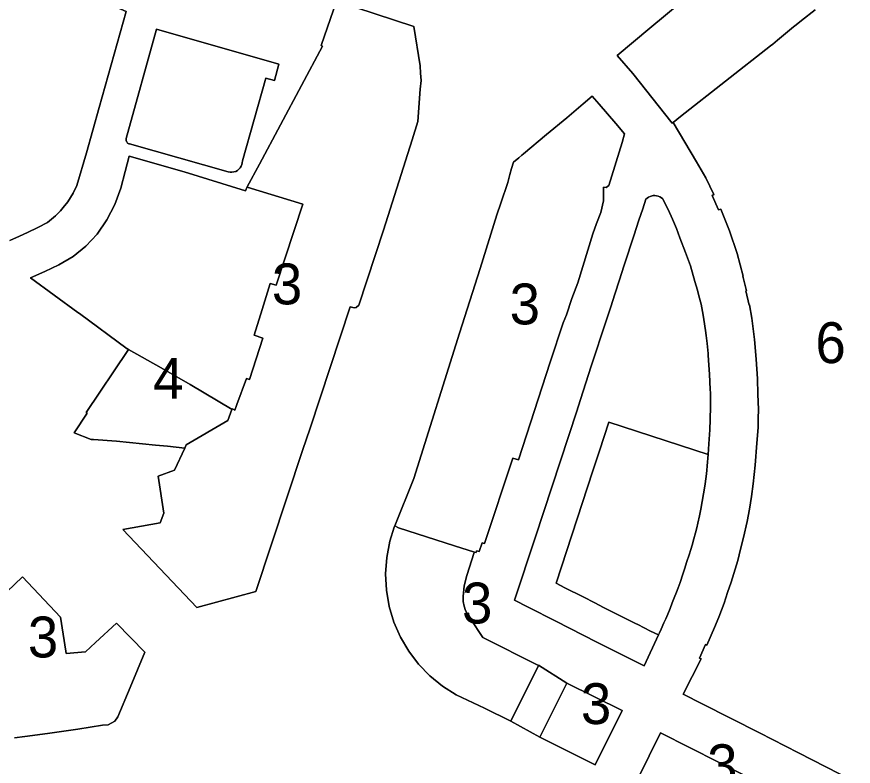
# Model space of a CAD drawing. Extents: x 598968 to 613553, y 4409678 to 4430833.
# Drawn here: x 608676.3 to 608922.1, y 4415660.4 to 4415880.5 of the extents above; entities that cross this region are included whole.
import ezdxf

# ---------------------------------------------------------------- set-up
doc = ezdxf.new("R2010")
doc.units = 0
for name, color, linetype in [('1', 7, 'Continuous'), ("ZONA 3. ILLES  D'EDIFICIS ENTRE MITGERES. EIXAMPLE.", 7, 'Continuous'), ('ZONA 4. CASES UNIFAMILIRAS AÏLLADES EN PARCEL.LES', 7, 'Continuous'), ('ZONA 6. EDIFICIS DE PISOS_ AÏLLATS I EN PARCEL.LES', 7, 'Continuous')]:
    doc.layers.add(name, color=color, linetype=linetype)

msp = doc.modelspace()

# ---------------------------------------------------------------- linework, layer by layer
at = {"layer": '1'}
for points in [[(608665.6671, 4415901.5846), (608685.7511, 4415892.1019), (608687.5781, 4415891.2393), (608708.4875, 4415882.0646), (608700.4769, 4415853.8357), (608696.8316, 4415840.5531), (608693.967, 4415830.9559), (608692.8471, 4415828.6759), (608691.2766, 4415826.1275), (608689.9771, 4415824.4759), (608689.1371, 4415823.5159), (608687.6621, 4415822.0085), (608685.3272, 4415820.1358), (608682.4791, 4415818.601), (608679.4873, 4415817.1158), (608677.0973, 4415816.0357), (608674.2812, 4415814.8108)], [(608674.2812, 4415814.8108), (608677.0973, 4415816.0357), (608679.4873, 4415817.1158), (608682.4791, 4415818.601), (608685.3272, 4415820.1358), (608687.6621, 4415822.0085), (608689.1371, 4415823.5159), (608689.9771, 4415824.4759), (608691.2766, 4415826.1275), (608692.8471, 4415828.6759), (608693.967, 4415830.9559), (608696.8316, 4415840.5531), (608700.4769, 4415853.8357), (608708.4875, 4415882.0646), (608687.5781, 4415891.2393), (608685.7511, 4415892.1019), (608665.6671, 4415901.5846)], [(608922.0848, 4415656.0922), (608905.99, 4415664.3368), (608894.5151, 4415670.2115), (608877.7153, 4415678.7311), (608872.1353, 4415681.591), (608877.3753, 4415691.9507), (608876.9253, 4415692.1009), (608878.7052, 4415696.1109), (608879.1052, 4415695.9309), (608881.2852, 4415701.1359), (608882.5452, 4415704.1709), (608884.1051, 4415708.2709), (608885.1701, 4415711.3809), (608886.2351, 4415714.4908), (608886.9751, 4415716.9608), (608888.125, 4415720.7908), (608888.975, 4415724.1608), (608889.825, 4415727.5307), (608890.885, 4415732.2807), (608891.575, 4415735.9307), (608892.1749, 4415739.6106), (608892.6949, 4415743.3005), (608893.3099, 4415748.8505), (608893.7999, 4415755.2954), (608894.1149, 4415759.8903), (608894.1798, 4415762.5103), (608894.2448, 4415765.1303), (608894.0898, 4415769.6302), (608893.9348, 4415774.1302), (608893.5148, 4415779.9251), (608893.0948, 4415785.72), (608892.2748, 4415791.9799), (608891.6248, 4415795.8898), (608891.4851, 4415795.8585), (608890.5548, 4415800.0098), (608890.7512, 4415800.0631), (608889.6329, 4415804.3124), (608889.7748, 4415804.3497), (608887.9355, 4415811.0367), (608885.7333, 4415817.6132), (608883.1748, 4415824.0593), (608882.5148, 4415823.7693), (608880.6374, 4415828.0603), (608881.1074, 4415828.2848), (608878.7649, 4415833.1899), (608876.0498, 4415837.899), (608869.1849, 4415849.4888), (608869.1711, 4415849.5075), (608868.9091, 4415849.305), (608857.3172, 4415863.8302), (608852.705, 4415869.1482), (608862.2966, 4415877.1663), (608880.7115, 4415892.5602)], [(608880.7115, 4415892.5602), (608862.2966, 4415877.1663), (608852.705, 4415869.1482), (608857.3172, 4415863.8302), (608868.9091, 4415849.305), (608869.1711, 4415849.5075), (608871.3507, 4415851.1924), (608897.7532, 4415871.9606), (608898.4164, 4415872.5136), (608899.7827, 4415873.6528), (608902.7647, 4415876.1135), (608904.5467, 4415877.5412), (608905.354, 4415878.1767), (608906.9198, 4415879.4233), (608910.9111, 4415882.606)], [(608668.766, 4415707.2863), (608677.9789, 4415716.0018), (608689.1975, 4415704.1274), (608690.7464, 4415694.2089), (608690.8575, 4415693.4976), (608696.4874, 4415693.9877), (608699.4574, 4415696.7377), (608705.6247, 4415702.4199), (608713.9672, 4415693.928), (608709.6773, 4415683.528), (608705.9674, 4415674.9031), (608705.1571, 4415673.6697), (608703.1374, 4415672.5681), (608701.5468, 4415672.4145), (608694.2775, 4415671.2879), (608685.3576, 4415669.9578), (608678.6577, 4415669.1077), (608675.6878, 4415668.7176)]]:
    msp.add_lwpolyline(points, dxfattribs=at)
for points in [[(608792.9757, 4415877.627), (608794.8358, 4415866.0772), (608794.9658, 4415863.9272), (608795.0958, 4415861.7773), (608794.8758, 4415859.2273), (608794.1058, 4415849.7874), (608792.4708, 4415844.3325), (608784.0394, 4415817.8481), (608776.7962, 4415795.7978), (608776.0162, 4415795.1628), (608775.4562, 4415795.0278), (608774.2862, 4415795.3177), (608762.4865, 4415759.728), (608760.2965, 4415753.118), (608746.5568, 4415711.7083), (608729.1804, 4415706.969), (608707.4372, 4415729.8974), (608718.4171, 4415731.8376), (608719.477, 4415734.6976), (608717.857, 4415745.5974), (608722.637, 4415747.3874), (608725.6469, 4415753.8374), (608720.607, 4415754.3773), (608717.03, 4415754.7409), (608705.6571, 4415755.897), (608698.8289, 4415756.3612), (608698.1572, 4415756.4069), (608693.206, 4415758.2991), (608697.0451, 4415764.139), (608696.6672, 4415764.3167), (608708.987, 4415782.4767), (608709.1674, 4415782.795), (608708.801, 4415783.0027), (608708.7968, 4415783.0051), (608694.7068, 4415793.3312), (608694.2728, 4415793.6492), (608680.3973, 4415803.8809), (608684.6014, 4415805.6813), (608688.7072, 4415807.696), (608692.8761, 4415810.1175), (608696.645, 4415813.1242), (608699.932, 4415816.6511), (608702.7673, 4415820.8825), (608705.1066, 4415825.407), (608706.9201, 4415830.1667), (608708.1845, 4415835.1008), (608709.303, 4415839.6027), (608725.5287, 4415834.9352), (608743.4712, 4415829.4286), (608743.9875, 4415830.5593), (608744.0068, 4415830.5533), (608747.6016, 4415837.2559), (608766.1502, 4415871.9266), (608765.7528, 4415872.0705), (608770.206, 4415885.1265)], [(608709.4768, 4415843.176), (608709.2696, 4415843.2285), (608709.0741, 4415843.3149), (608708.8958, 4415843.4327), (608708.7396, 4415843.5786), (608708.61, 4415843.7486), (608708.5106, 4415843.9377), (608708.4443, 4415844.1408), (608708.4127, 4415844.3522), (608708.417, 4415844.5659), (608708.4568, 4415844.7759), (608717.3892, 4415876.872), (608753.3367, 4415866.6065), (608752.0263, 4415861.8065), (608749.5363, 4415862.4965), (608742.6165, 4415838.2266), (608742.5856, 4415837.6675), (608742.4603, 4415837.1217), (608742.244, 4415836.6051), (608741.9432, 4415836.1328), (608741.5665, 4415835.7184), (608741.1249, 4415835.374), (608740.6313, 4415835.1096), (608740.0999, 4415834.9329), (608739.5462, 4415834.849), (608738.9863, 4415834.8603), (608738.4365, 4415834.9666)], [(608753.3367, 4415866.6065), (608717.3892, 4415876.872), (608708.4568, 4415844.7759), (608708.417, 4415844.5659), (608708.4127, 4415844.3522), (608708.4443, 4415844.1408), (608708.5106, 4415843.9377), (608708.61, 4415843.7486), (608708.7396, 4415843.5786), (608708.8958, 4415843.4327), (608709.0741, 4415843.3149), (608709.2696, 4415843.2285), (608709.4768, 4415843.176), (608738.4365, 4415834.9666), (608738.9863, 4415834.8603), (608739.5462, 4415834.849), (608740.0999, 4415834.9329), (608740.6313, 4415835.1096), (608741.1249, 4415835.374), (608741.5665, 4415835.7184), (608741.9432, 4415836.1328), (608742.244, 4415836.6051), (608742.4603, 4415837.1217), (608742.5856, 4415837.6675), (608742.6165, 4415838.2266), (608749.5363, 4415862.4965), (608752.0263, 4415861.8065)], [(608812.4654, 4415806.5784), (608817.3756, 4415822.3482), (608818.5327, 4415825.7991), (608820.5456, 4415831.7981), (608821.1547, 4415834.1919), (608821.7102, 4415835.9529), (608822.2955, 4415837.8081), (608823.8361, 4415839.1014), (608824.7465, 4415839.8656), (608825.2123, 4415840.2567), (608831.953, 4415845.9157), (608837.9052, 4415850.8382), (608842.7752, 4415854.9682), (608845.3801, 4415857.1987), (608847.4307, 4415854.8189), (608852.3263, 4415849.1431), (608854.893, 4415846.1663), (608854.1451, 4415843.6186), (608850.2392, 4415830.9477), (608849.4641, 4415830.3639), (608848.7011, 4415830.5188), (608848.7039, 4415826.4498), (608847.8891, 4415822.9861), (608846.6809, 4415819.804), (608845.6053, 4415816.8088), (608841.1754, 4415802.3989), (608839.3754, 4415797.8089), (608837.8504, 4415793.0189), (608836.8854, 4415790.6189), (608833.0655, 4415779.119), (608823.7367, 4415750.4019), (608822.0858, 4415750.9192), (608813.766, 4415725.7994), (608813.3288, 4415725.9349), (608813.056, 4415726.0291), (608812.216, 4415723.4394), (608811.3936, 4415723.6594), (608811.266, 4415723.1394), (608810.7948, 4415723.2858), (608810.7444, 4415723.1336), (608808.556, 4415716.4594), (608807.7803, 4415713.3736), (608807.4461, 4415710.2095), (608807.4963, 4415708.8058), (608807.7432, 4415707.4231), (608808.1819, 4415706.0887), (608808.8036, 4415704.8293), (608809.5961, 4415703.6696), (608813.296, 4415698.1897), (608829.5558, 4415690.0201), (608829.588, 4415690.0856), (608837.9157, 4415684.7703), (608854.162, 4415676.7139), (608846.2557, 4415660.7708), (608829.9683, 4415668.9556), (608821.4948, 4415673.6487), (608821.466, 4415673.5902), (608813.7061, 4415677.47), (608805.3962, 4415681.3198), (608801.3679, 4415683.9017), (608797.6709, 4415686.9391), (608794.3563, 4415690.3898), (608791.4701, 4415694.206), (608789.0523, 4415698.3349), (608787.1363, 4415702.7192), (608785.7608, 4415707.3407), (608784.9421, 4415712.0925), (608784.6918, 4415716.9079), (608785.0134, 4415721.719), (608785.9024, 4415726.4582), (608787.2064, 4415730.6129), (608787.2779, 4415730.8406), (608787.3463, 4415731.0588), (608787.363, 4415731.049), (608793.0161, 4415744.8987), (608806.4059, 4415787.5784)], [(608744.0068, 4415830.5533), (608743.9875, 4415830.5593), (608743.4712, 4415829.4286), (608725.5287, 4415834.9352), (608709.303, 4415839.6027), (608708.1845, 4415835.1008), (608706.9201, 4415830.1667), (608705.1066, 4415825.407), (608702.7673, 4415820.8825), (608699.932, 4415816.6511), (608696.645, 4415813.1242), (608692.8761, 4415810.1175), (608688.7072, 4415807.696), (608684.6014, 4415805.6813), (608680.3973, 4415803.8809), (608694.2728, 4415793.6492), (608694.7068, 4415793.3312), (608708.7968, 4415783.0051), (608708.801, 4415783.0027), (608709.1674, 4415782.795), (608709.1742, 4415782.807), (608718.7341, 4415777.3734), (608718.752, 4415777.3632), (608727.2113, 4415772.5395), (608739.5525, 4415765.1829), (608739.5352, 4415765.1375), (608739.7349, 4415765.3464), (608740.3581, 4415764.9873), (608740.8993, 4415766.3654), (608741.0167, 4415766.6875), (608743.7766, 4415774.2575), (608744.6966, 4415773.9575), (608748.6465, 4415786.1674), (608746.0866, 4415786.9873), (608748.4215, 4415794.5773), (608750.7565, 4415802.1672), (608752.5664, 4415801.6473), (608760.3767, 4415825.4483), (608743.9765, 4415830.4968)], [(608840.8271, 4415764.7093), (608841.2426, 4415765.9879), (608842.7283, 4415770.5526), (608845.1213, 4415777.9042), (608846.6397, 4415782.5694), (608847.9253, 4415786.5192), (608849.6878, 4415791.8175), (608850.8653, 4415795.3573), (608852.0446, 4415799.0167), (608853.406, 4415803.2726), (608854.7061, 4415807.2897), (608855.855, 4415810.8024), (608856.6472, 4415813.2251), (608857.6205, 4415816.2008), (608859.1048, 4415820.7458), (608860.2137, 4415824.1501), (608861.135, 4415826.9789), (608861.915, 4415827.5689), (608862.365, 4415827.7789), (608863.315, 4415828.0089), (608863.56, 4415828.0139), (608863.805, 4415828.0189), (608864.775, 4415827.849), (608865.235, 4415827.669), (608866.055, 4415827.129), (608867.715, 4415823.9191), (608868.955, 4415821.1041), (608870.195, 4415818.2892), (608871.1736, 4415815.6391), (608872.7812, 4415811.2861), (608874.2349, 4415807.3494), (608875.5749, 4415802.8095), (608876.3049, 4415800.1995), (608876.7349, 4415798.5295), (608877.3797, 4415796.0976), (608877.9527, 4415792.916), (608878.1669, 4415791.5695), (608878.6417, 4415788.3662), (608878.865, 4415786.8597), (608879.1115, 4415784.5844), (608879.4291, 4415781.6538), (608879.475, 4415781.2298), (608879.5846, 4415779.5971), (608879.855, 4415775.5699), (608880.0783, 4415771.0537), (608880.125, 4415770.11), (608880.1435, 4415768.7625), (608880.1604, 4415767.5331), (608880.1675, 4415766.0152), (608880.0885, 4415762.2281), (608879.955, 4415759.1901), (608879.6507, 4415755.0622), (608879.4304, 4415751.9321), (608879.1951, 4415748.5902), (608879.042, 4415747.2914), (608878.8312, 4415745.5025), (608878.4951, 4415742.6503), (608877.3151, 4415735.8604), (608876.8846, 4415733.9723), (608876.3842, 4415731.7776), (608876.0763, 4415730.4266), (608875.6908, 4415728.96), (608875.2102, 4415727.1555), (608874.7158, 4415725.2991), (608874.3752, 4415724.0205), (608873.8655, 4415722.4677), (608873.2232, 4415720.5112), (608872.4867, 4415718.2675), (608872.0073, 4415716.8071), (608871.2069, 4415714.3687), (608870.6219, 4415712.8204), (608870.134, 4415711.5564), (608869.4782, 4415709.8572), (608868.9153, 4415708.4006), (608868.2754, 4415706.741), (608867.6153, 4415705.0306), (608867.0013, 4415703.6924), (608866.4526, 4415702.4962), (608865.6141, 4415700.6685), (608865.1133, 4415699.5771), (608864.828, 4415698.9553), (608860.6555, 4415689.8607), (608846.7356, 4415696.8503), (608834.6657, 4415702.985), (608826.6074, 4415707.0808), (608822.5959, 4415709.1198), (608828.6357, 4415727.5096), (608836.0406, 4415750.1094)], [(608879.4304, 4415751.9321), (608879.6507, 4415755.0622), (608879.955, 4415759.1901), (608880.0885, 4415762.2281), (608880.1675, 4415766.0152), (608880.1604, 4415767.5331), (608880.1435, 4415768.7625), (608880.125, 4415770.11), (608880.0783, 4415771.0537), (608879.855, 4415775.5699), (608879.5846, 4415779.5971), (608879.475, 4415781.2298), (608879.4291, 4415781.6538), (608879.1115, 4415784.5844), (608878.865, 4415786.8597), (608878.6417, 4415788.3662), (608878.1669, 4415791.5695), (608877.9527, 4415792.916), (608877.3797, 4415796.0976), (608876.7349, 4415798.5295), (608876.3049, 4415800.1995), (608875.5749, 4415802.8095), (608874.2349, 4415807.3494), (608872.7812, 4415811.2861), (608871.1736, 4415815.6391), (608870.195, 4415818.2892), (608868.955, 4415821.1041), (608867.715, 4415823.9191), (608866.055, 4415827.129), (608865.235, 4415827.669), (608864.775, 4415827.849), (608863.805, 4415828.0189), (608863.56, 4415828.0139), (608863.315, 4415828.0089), (608862.365, 4415827.7789), (608861.915, 4415827.5689), (608861.135, 4415826.9789), (608860.2137, 4415824.1501), (608859.1048, 4415820.7458), (608857.6205, 4415816.2008), (608856.6472, 4415813.2251), (608855.855, 4415810.8024), (608854.7061, 4415807.2897), (608853.406, 4415803.2726), (608852.0446, 4415799.0167), (608850.8653, 4415795.3573), (608849.6878, 4415791.8175), (608847.9253, 4415786.5192), (608846.6397, 4415782.5694), (608845.1213, 4415777.9042), (608842.7283, 4415770.5526), (608841.2426, 4415765.9879), (608840.8271, 4415764.7093), (608836.0406, 4415750.1094), (608828.6357, 4415727.5096), (608822.5959, 4415709.1198), (608826.6074, 4415707.0808), (608834.6657, 4415702.985), (608846.7356, 4415696.8503), (608860.6555, 4415689.8607), (608864.828, 4415698.9553), (608862.5328, 4415700.1079), (608858.7675, 4415701.9985), (608858.0659, 4415702.3509), (608851.2813, 4415705.7629), (608851.2671, 4415705.77), (608848.7204, 4415707.059), (608846.1367, 4415708.3723), (608842.7097, 4415710.114), (608837.3604, 4415712.8329), (608834.7727, 4415714.1481), (608845.6051, 4415747.1867), (608847.5223, 4415753.035), (608850.2681, 4415761.4102)], [(608879.4304, 4415751.9321), (608850.2681, 4415761.4102), (608847.5223, 4415753.035), (608845.6051, 4415747.1867), (608834.7727, 4415714.1481), (608837.3604, 4415712.8329), (608842.7097, 4415710.114), (608846.1367, 4415708.3723), (608848.7204, 4415707.059), (608851.2671, 4415705.77), (608851.2813, 4415705.7629), (608858.0659, 4415702.3509), (608858.7675, 4415701.9985), (608862.5328, 4415700.1079), (608864.828, 4415698.9553), (608865.1133, 4415699.5771), (608865.6141, 4415700.6685), (608866.4526, 4415702.4962), (608867.0013, 4415703.6924), (608867.6153, 4415705.0306), (608868.2754, 4415706.741), (608868.9153, 4415708.4006), (608869.4782, 4415709.8572), (608870.134, 4415711.5564), (608870.6219, 4415712.8204), (608871.2069, 4415714.3687), (608872.0073, 4415716.8071), (608872.4867, 4415718.2675), (608873.2232, 4415720.5112), (608873.8655, 4415722.4677), (608874.3752, 4415724.0205), (608874.7158, 4415725.2991), (608875.2102, 4415727.1555), (608875.6908, 4415728.96), (608876.0763, 4415730.4266), (608876.3842, 4415731.7776), (608876.8846, 4415733.9723), (608877.3151, 4415735.8604), (608878.4951, 4415742.6503), (608878.8312, 4415745.5025), (608879.042, 4415747.2914), (608879.1951, 4415748.5902)], [(608837.9157, 4415684.7703), (608829.588, 4415690.0856), (608829.5558, 4415690.0201), (608821.4948, 4415673.6487), (608829.9683, 4415668.9556)], [(608865.4655, 4415670.151), (608899.5386, 4415652.9888), (608892.7452, 4415639.5019), (608858.7456, 4415656.6811)]]:
    msp.add_lwpolyline(points, close=True, dxfattribs=at)
at = {"layer": "ZONA 3. ILLES  D'EDIFICIS ENTRE MITGERES. EIXAMPLE."}
for points in [[(608725.6469, 4415753.8374), (608722.637, 4415747.3874), (608717.857, 4415745.5974), (608719.477, 4415734.6976), (608718.4171, 4415731.8376), (608707.4372, 4415729.8974), (608729.1804, 4415706.969), (608746.5568, 4415711.7083), (608760.2965, 4415753.118), (608762.4865, 4415759.728), (608774.2862, 4415795.3177), (608775.4562, 4415795.0278), (608776.0162, 4415795.1628), (608776.7962, 4415795.7978), (608784.0394, 4415817.8481), (608792.4708, 4415844.3325), (608794.1058, 4415849.7874), (608794.8758, 4415859.2273), (608795.0958, 4415861.7773), (608794.9658, 4415863.9272), (608794.8358, 4415866.0772), (608792.9757, 4415877.627), (608770.206, 4415885.1265), (608765.7528, 4415872.0705), (608766.1502, 4415871.9266), (608747.6016, 4415837.2559), (608744.0068, 4415830.5533), (608743.9765, 4415830.4968), (608760.3767, 4415825.4483), (608752.5664, 4415801.6473), (608750.7565, 4415802.1672), (608748.4215, 4415794.5773), (608746.0866, 4415786.9873), (608748.6465, 4415786.1674), (608744.6966, 4415773.9575), (608743.7766, 4415774.2575), (608741.0167, 4415766.6875), (608740.8993, 4415766.3654), (608740.3581, 4415764.9873), (608739.7349, 4415765.3464), (608739.5352, 4415765.1375), (608738.3367, 4415761.9875), (608726.1269, 4415754.7774)], [(608810.7948, 4415723.2858), (608811.266, 4415723.1394), (608811.3936, 4415723.6594), (608812.216, 4415723.4394), (608813.056, 4415726.0291), (608813.3288, 4415725.9349), (608813.766, 4415725.7994), (608822.0858, 4415750.9192), (608823.7367, 4415750.4019), (608833.0655, 4415779.119), (608836.8854, 4415790.6189), (608837.8504, 4415793.0189), (608839.3754, 4415797.8089), (608841.1754, 4415802.3989), (608845.6053, 4415816.8088), (608846.6809, 4415819.804), (608847.8891, 4415822.9861), (608848.7039, 4415826.4498), (608848.7011, 4415830.5188), (608849.4641, 4415830.3639), (608850.2392, 4415830.9477), (608854.1451, 4415843.6186), (608854.893, 4415846.1663), (608852.3263, 4415849.1431), (608847.4307, 4415854.8189), (608845.3801, 4415857.1987), (608842.7752, 4415854.9682), (608837.9052, 4415850.8382), (608831.953, 4415845.9157), (608825.2123, 4415840.2567), (608824.7465, 4415839.8656), (608823.8361, 4415839.1014), (608822.2955, 4415837.8081), (608821.7102, 4415835.9529), (608821.1547, 4415834.1919), (608820.5456, 4415831.7981), (608818.5327, 4415825.7991), (608817.3756, 4415822.3482), (608812.4654, 4415806.5784), (608806.4059, 4415787.5784), (608793.0161, 4415744.8987), (608787.363, 4415731.049), (608788.4562, 4415730.4089), (608804.9461, 4415725.1092), (608810.796, 4415723.2894)], [(608787.363, 4415731.049), (608787.3463, 4415731.0588), (608787.2779, 4415730.8406), (608787.2064, 4415730.6129), (608785.9024, 4415726.4582), (608785.0134, 4415721.719), (608784.6918, 4415716.9079), (608784.9421, 4415712.0925), (608785.7608, 4415707.3407), (608787.1363, 4415702.7192), (608789.0523, 4415698.3349), (608791.4701, 4415694.206), (608794.3563, 4415690.3898), (608797.6709, 4415686.9391), (608801.3679, 4415683.9017), (608805.3962, 4415681.3198), (608813.7061, 4415677.47), (608821.466, 4415673.5902), (608821.4948, 4415673.6487), (608829.5558, 4415690.0201), (608813.296, 4415698.1897), (608809.5961, 4415703.6696), (608808.8036, 4415704.8293), (608808.1819, 4415706.0887), (608807.7432, 4415707.4231), (608807.4963, 4415708.8058), (608807.4461, 4415710.2095), (608807.7803, 4415713.3736), (608808.556, 4415716.4594), (608810.7444, 4415723.1336), (608810.7948, 4415723.2858), (608810.796, 4415723.2894), (608804.9461, 4415725.1092), (608788.4562, 4415730.4089)], [(608829.9683, 4415668.9556), (608846.2557, 4415660.7708), (608854.162, 4415676.7139), (608837.9157, 4415684.7703)], [(608899.5386, 4415652.9888), (608865.4655, 4415670.151), (608858.7456, 4415656.6811), (608892.7452, 4415639.5019)]]:
    msp.add_lwpolyline(points, close=True, dxfattribs=at)
msp.add_lwpolyline([(608675.6878, 4415668.7176), (608678.6577, 4415669.1077), (608685.3576, 4415669.9578), (608694.2775, 4415671.2879), (608701.5468, 4415672.4145), (608703.1374, 4415672.5681), (608705.1571, 4415673.6697), (608705.9674, 4415674.9031), (608709.6773, 4415683.528), (608713.9672, 4415693.928), (608705.6247, 4415702.4199), (608699.4574, 4415696.7377), (608696.4874, 4415693.9877), (608690.8575, 4415693.4976), (608690.7464, 4415694.2089), (608689.1975, 4415704.1274), (608677.9789, 4415716.0018), (608668.766, 4415707.2863)], dxfattribs=at)
at = {"layer": 'ZONA 4. CASES UNIFAMILIRAS AÏLLADES EN PARCEL.LES'}
msp.add_lwpolyline([(608739.5352, 4415765.1375), (608739.5525, 4415765.1829), (608727.2113, 4415772.5395), (608718.752, 4415777.3632), (608718.7341, 4415777.3734), (608709.1742, 4415782.807), (608709.1674, 4415782.795), (608708.987, 4415782.4767), (608696.6672, 4415764.3167), (608697.0451, 4415764.139), (608693.206, 4415758.2991), (608698.1572, 4415756.4069), (608698.8289, 4415756.3612), (608705.6571, 4415755.897), (608717.03, 4415754.7409), (608720.607, 4415754.3773), (608725.6469, 4415753.8374), (608726.1269, 4415754.7774), (608738.3367, 4415761.9875)], close=True, dxfattribs=at)
at = {"layer": 'ZONA 6. EDIFICIS DE PISOS_ AÏLLATS I EN PARCEL.LES'}
msp.add_lwpolyline([(608910.9111, 4415882.606), (608906.9198, 4415879.4233), (608905.354, 4415878.1767), (608904.5467, 4415877.5412), (608902.7647, 4415876.1135), (608899.7827, 4415873.6528), (608898.4164, 4415872.5136), (608897.7532, 4415871.9606), (608871.3507, 4415851.1924), (608869.1711, 4415849.5075), (608869.1849, 4415849.4888), (608876.0498, 4415837.899), (608878.7649, 4415833.1899), (608881.1074, 4415828.2848), (608880.6374, 4415828.0603), (608882.5148, 4415823.7693), (608883.1748, 4415824.0593), (608885.7333, 4415817.6132), (608887.9355, 4415811.0367), (608889.7748, 4415804.3497), (608889.6329, 4415804.3124), (608890.7512, 4415800.0631), (608890.5548, 4415800.0098), (608891.4851, 4415795.8585), (608891.6248, 4415795.8898), (608892.2748, 4415791.9799), (608893.0948, 4415785.72), (608893.5148, 4415779.9251), (608893.9348, 4415774.1302), (608894.0898, 4415769.6302), (608894.2448, 4415765.1303), (608894.1798, 4415762.5103), (608894.1149, 4415759.8903), (608893.7999, 4415755.2954), (608893.3099, 4415748.8505), (608892.6949, 4415743.3005), (608892.1749, 4415739.6106), (608891.575, 4415735.9307), (608890.885, 4415732.2807), (608889.825, 4415727.5307), (608888.975, 4415724.1608), (608888.125, 4415720.7908), (608886.9751, 4415716.9608), (608886.2351, 4415714.4908), (608885.1701, 4415711.3809), (608884.1051, 4415708.2709), (608882.5452, 4415704.1709), (608881.2852, 4415701.1359), (608879.1052, 4415695.9309), (608878.7052, 4415696.1109), (608876.9253, 4415692.1009), (608877.3753, 4415691.9507), (608872.1353, 4415681.591), (608877.7153, 4415678.7311), (608894.5151, 4415670.2115), (608905.99, 4415664.3368), (608922.0848, 4415656.0922)], dxfattribs=at)

# ---------------------------------------------------------------- texts
at = {"layer": "ZONA 3. ILLES  D'EDIFICIS ENTRE MITGERES. EIXAMPLE."}
for p in [(608751.2665, 4415796.0477), (608821.128, 4415790.169), (608807.1238, 4415702.3245), (608679.5697, 4415692.3492), (608842.0651, 4415672.7706), (608879.1421, 4415654.8265)]:
    msp.add_text('3', height=12, dxfattribs=at).set_placement(p)
at = {"layer": 'ZONA 4. CASES UNIFAMILIRAS AÏLLADES EN PARCEL.LES'}
msp.add_text('4', height=12, dxfattribs=at).set_placement((608716.3793, 4415768.3222))
at = {"layer": 'ZONA 6. EDIFICIS DE PISOS_ AÏLLATS I EN PARCEL.LES'}
msp.add_text('6', height=12, dxfattribs=at).set_placement((608910.9605, 4415778.7919))

doc.saveas('drawing.dxf')
